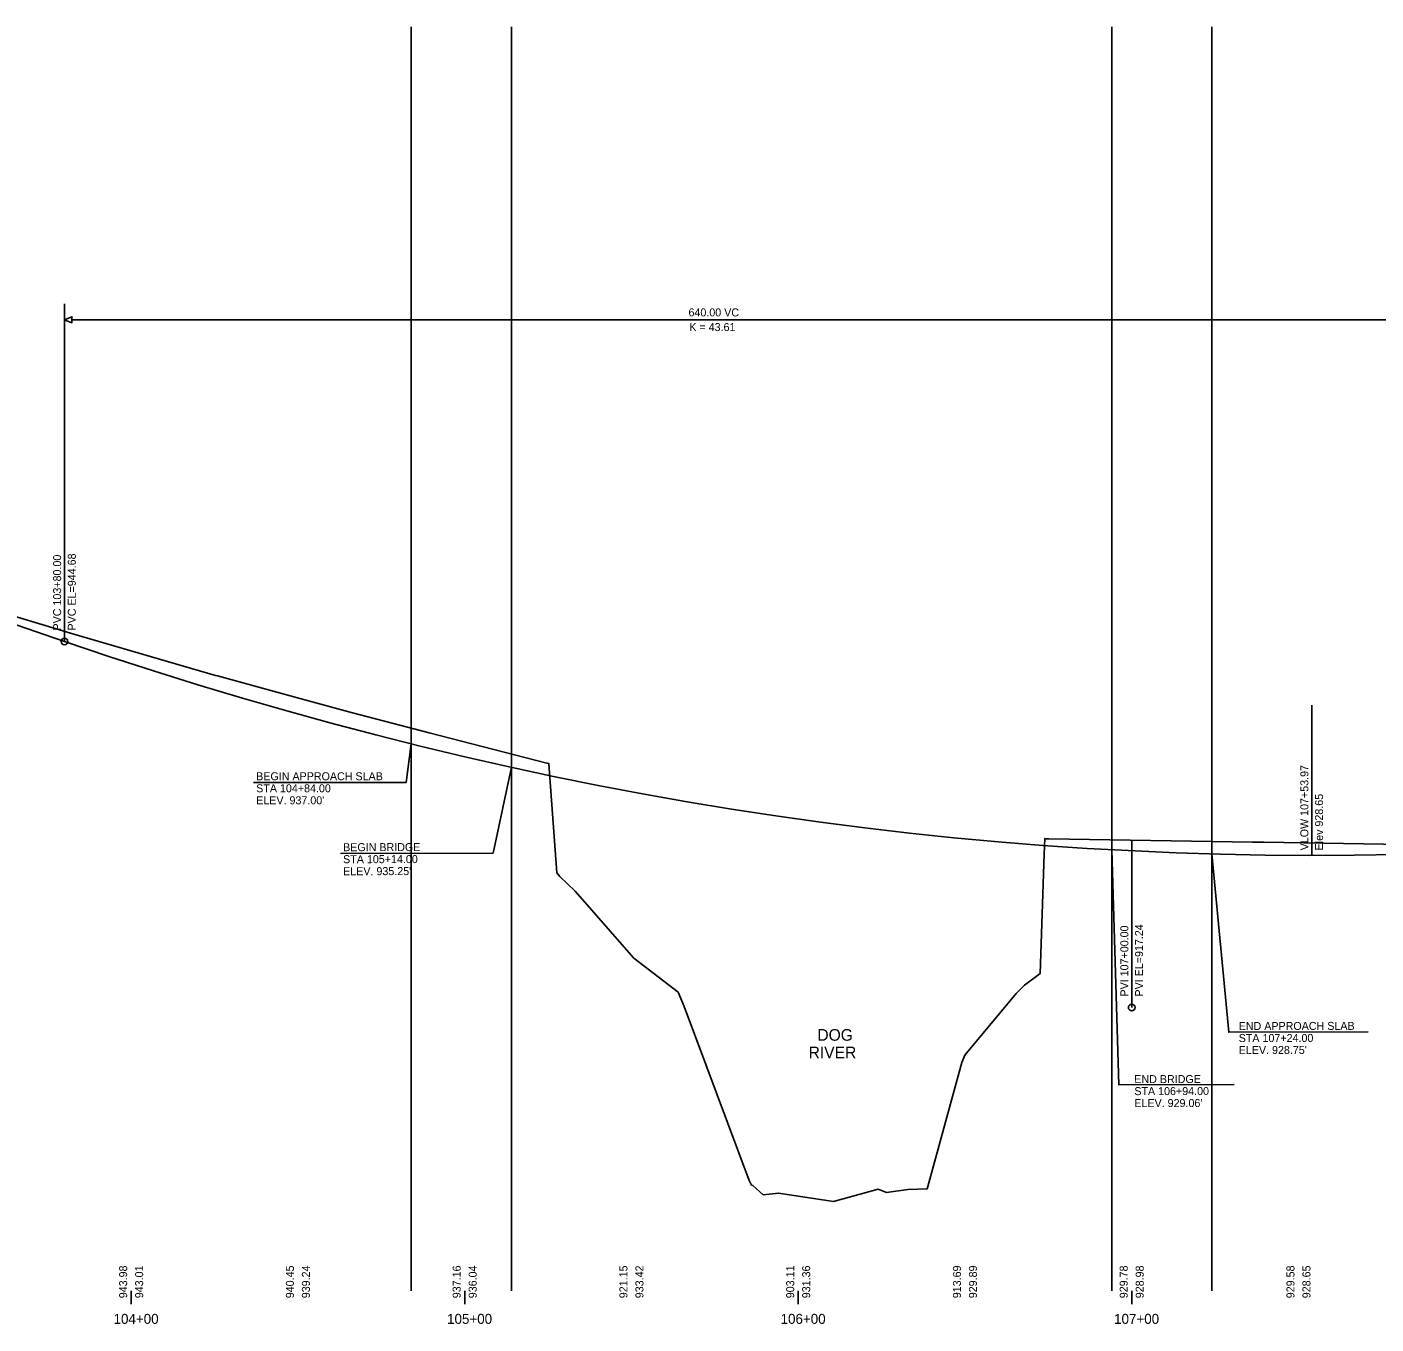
# Model space of a CAD drawing. Extents: x 2091593 to 2093109, y 1330214 to 1331965.
# Drawn here: x 2091968.5 to 2092372.9, y 1331544.3 to 1331933.2 of the extents above; entities that cross this region are included whole.
import ezdxf

# ---------------------------------------------------------------- set-up
doc = ezdxf.new("R2010")
doc.units = 0
for name, color, linetype in [('ATMS_P_ITS-Device-and-Conduit', 7, 'Continuous'), ('ATMS_P_Utility-Text', 7, 'Continuous'), ('PROF_E_Ground-Line', 7, 'Continuous'), ('PROF_E_Ground-Text', 7, 'Continuous'), ('PROF_P_CONSTCL-Cell', 7, 'Continuous'), ('PROF_P_CONSTCL-Line', 7, 'Continuous'), ('PROF_P_Finish-Elev-Text', 7, 'Continuous'), ('PROF_P_Finish-Text', 7, 'Continuous'), ('SHT_B_Grid-Station-Text', 7, 'Continuous'), ('SHT_B_Major-Station-Tic-Line', 7, 'Continuous')]:
    doc.layers.add(name, color=color, linetype=linetype)

msp = doc.modelspace()

# ---------------------------------------------------------------- linework, layer by layer
at = {"layer": 'ATMS_P_ITS-Device-and-Conduit'}
for p, q in [((2092083.69, 1331554.21), (2092083.69, 1331933.2)), ((2092113.69, 1331554.21), (2092113.69, 1331933.2)), ((2092293.69, 1331554.21), (2092293.69, 1331933.2)), ((2092323.69, 1331554.21), (2092323.69, 1331933.2))]:
    msp.add_line(p, q, dxfattribs=at)
at = {"layer": 'PROF_E_Ground-Line'}
msp.add_lwpolyline([(2091934.7, 1331765.56), (2091982.53, 1331751.11), (2092025, 1331738.75), (2092025.61, 1331738.58), (2092048.43, 1331732.34), (2092066.01, 1331727.52), (2092066.44, 1331727.41), (2092066.5, 1331727.39), (2092089.01, 1331721.58), (2092124.34, 1331712.48), (2092124.95, 1331712.32), (2092124.95, 1331712.32), (2092124.95, 1331712.32), (2092124.95, 1331712.31), (2092124.95, 1331712.29), (2092127.34, 1331679.56), (2092128.24, 1331678.45), (2092132.78, 1331674.07), (2092150.44, 1331653.93), (2092163.72, 1331643.76), (2092165.47, 1331639.52), (2092185.02, 1331587.34), (2092185.74, 1331585.89), (2092186.14, 1331585.81), (2092189.21, 1331582.97), (2092193.77, 1331583.53), (2092210.28, 1331581.02), (2092223.67, 1331584.75), (2092226.13, 1331583.74), (2092232.61, 1331584.6), (2092238.32, 1331584.78), (2092238.54, 1331585.48), (2092248.75, 1331622.69), (2092249.61, 1331624.86), (2092265.03, 1331643.41), (2092267.54, 1331645.86), (2092272.25, 1331649.35), (2092273.4, 1331685.11), (2092273.64, 1331689.81), (2092273.64, 1331689.81), (2092273.64, 1331689.81), (2092274.08, 1331689.79), (2092274.87, 1331689.77), (2092335.95, 1331688.72), (2092337.03, 1331688.71), (2092339.3, 1331688.72), (2092381.17, 1331688.01)], dxfattribs=at)
at = {"layer": 'PROF_P_CONSTCL-Cell'}
for centre in [(2091979.69, 1331748.93), (2092299.69, 1331639.17)]:
    msp.add_circle(centre, 1, dxfattribs=at)
at = {"layer": 'PROF_P_CONSTCL-Line'}
msp.add_line((2091929.69, 1331766.08), (2091979.69, 1331748.93), dxfattribs=at)
msp.add_lwpolyline([(2091979.69, 1331748.93), (2091993.03, 1331744.43), (2092006.36, 1331740.1), (2092019.69, 1331735.94), (2092033.03, 1331731.94), (2092046.36, 1331728.1), (2092059.69, 1331724.42), (2092073.03, 1331720.91), (2092086.36, 1331717.56), (2092099.69, 1331714.37), (2092113.03, 1331711.34), (2092126.36, 1331708.48), (2092139.69, 1331705.79), (2092153.03, 1331703.25), (2092166.36, 1331700.88), (2092179.69, 1331698.67), (2092193.03, 1331696.62), (2092206.36, 1331694.74), (2092219.69, 1331693.02), (2092233.03, 1331691.46), (2092246.36, 1331690.07), (2092259.69, 1331688.84), (2092273.03, 1331687.77), (2092286.36, 1331686.87), (2092313.03, 1331685.55), (2092326.36, 1331685.13), (2092339.69, 1331684.88), (2092353.03, 1331684.79), (2092366.36, 1331684.86), (2092379.69, 1331685.1)], dxfattribs=at)
at = {"layer": 'PROF_P_Finish-Text'}
for p, q in [((2091979.69, 1331748.93), (2091979.69, 1331850.21)), ((2091979.69, 1331748.93), (2091979.69, 1331796.93)), ((2092353.66, 1331684.79), (2092353.66, 1331729.79)), ((2092299.69, 1331639.17), (2092299.69, 1331689.17))]:
    msp.add_line(p, q, dxfattribs=at)
msp.add_lwpolyline([(2091979.69, 1331845.41), (2091981.91, 1331844.49), (2091981.91, 1331846.32)], close=True, dxfattribs=at)
for points in [[(2091981.91, 1331845.41), (2092617.48, 1331845.41)], [(2092036.42, 1331706.65), (2092082.17, 1331706.65), (2092083.69, 1331718.23)], [(2092062.47, 1331685.38), (2092108.23, 1331685.46), (2092113.69, 1331711.2)], [(2092330.38, 1331616.08), (2092295.81, 1331616.02), (2092293.69, 1331686.5)], [(2092370.64, 1331631.83), (2092328.77, 1331631.75), (2092323.69, 1331685.21)]]:
    msp.add_lwpolyline(points, dxfattribs=at)
at = {"layer": 'SHT_B_Major-Station-Tic-Line'}
for p, q in [((2091999.69, 1331550.21), (2091999.69, 1331554.21)), ((2092099.69, 1331550.21), (2092099.69, 1331554.21)), ((2092199.69, 1331550.21), (2092199.69, 1331554.21)), ((2092299.69, 1331550.21), (2092299.69, 1331554.21))]:
    msp.add_line(p, q, dxfattribs=at)

# ---------------------------------------------------------------- texts
at = {"layer": 'ATMS_P_Utility-Text'}
for s, p in [('DOG', (2092205.44, 1331629.21)), ('RIVER', (2092202.81, 1331623.96))]:
    msp.add_text(s, height=3.5, dxfattribs=at).set_placement(p)
at = {"layer": 'PROF_E_Ground-Text'}
for s, p in [('  943.98', (2091998.49, 1331550.21)), ('  940.45', (2092048.49, 1331550.21)), ('  937.16', (2092098.49, 1331550.21)), ('  921.15', (2092148.49, 1331550.21)), ('  903.11', (2092198.49, 1331550.21)), ('  913.69', (2092248.49, 1331550.21)), ('  929.78', (2092298.49, 1331550.21)), ('  929.58', (2092348.49, 1331550.21))]:
    msp.add_text(s, height=2.4, rotation=90, dxfattribs=at).set_placement(p)
at = {"layer": 'PROF_P_Finish-Elev-Text'}
for s, p in [('  943.01', (2092003.29, 1331550.21)), ('  939.24', (2092053.29, 1331550.21)), ('  936.04', (2092103.29, 1331550.21)), ('  933.42', (2092153.29, 1331550.21)), ('  931.36', (2092203.29, 1331550.21)), ('  929.89', (2092253.29, 1331550.21)), ('  928.98', (2092303.29, 1331550.21)), ('  928.65', (2092353.29, 1331550.21))]:
    msp.add_text(s, height=2.4, rotation=90, dxfattribs=at).set_placement(p)
at = {"layer": 'PROF_P_Finish-Text'}
for s, p in [('640.00 VC', (2092166.8, 1331846.41)), ('K = 43.61', (2092167.05, 1331842.01))]:
    msp.add_text(s, height=2.4, dxfattribs=at).set_placement(p)
for s, height, rotation, p in [('  PVC 103+80.00', 2.4, 90, (2091978.69, 1331750.43)), ('  PVC EL=944.68', 2.4, 90, (2091983.09, 1331750.43)), ('VLOW 107+53.97', 2.4, 90, (2092352.66, 1331686.29)), ('BEGIN APPROACH SLAB', 2.3994, 360, (2092037.18, 1331707.31)), ('STA 104+84.00', 2.3994, 360, (2092037.18, 1331703.71)), ("ELEV. 937.00'", 2.3994, 360, (2092037.18, 1331700.11)), ('Elev 928.65', 2.4, 90, (2092357.06, 1331686.29)), ('BEGIN BRIDGE', 2.3994, 0.1056, (2092063.24, 1331686.04)), ('STA 105+14.00', 2.3994, 0.1056, (2092063.24, 1331682.44)), ("ELEV. 935.25'", 2.3994, 0.1056, (2092063.25, 1331678.84)), ('  PVI 107+00.00', 2.4, 90, (2092298.69, 1331640.67)), ('  PVI EL=917.24', 2.4, 90, (2092303.09, 1331640.67)), ('END APPROACH SLAB', 2.3994, 0.1056, (2092331.77, 1331632.41)), ('STA 107+24.00', 2.3994, 0.1056, (2092331.78, 1331628.81)), ("ELEV. 928.75'", 2.3994, 0.1056, (2092331.78, 1331625.21)), ('END BRIDGE', 2.399, 0.1056, (2092300.47, 1331616.49)), ('STA 106+94.00', 2.3994, 0.1056, (2092300.48, 1331612.89)), ("ELEV. 929.06'", 2.3994, 0.1056, (2092300.48, 1331609.3))]:
    msp.add_text(s, height=height, rotation=rotation, dxfattribs=at).set_placement(p)
at = {"layer": 'SHT_B_Grid-Station-Text'}
for s, p in [('104+00', (2091994.42, 1331544.31)), ('105+00', (2092094.42, 1331544.31)), ('106+00', (2092194.42, 1331544.31)), ('107+00', (2092294.42, 1331544.31))]:
    msp.add_text(s, height=3, dxfattribs=at).set_placement(p)

doc.saveas('drawing.dxf')
